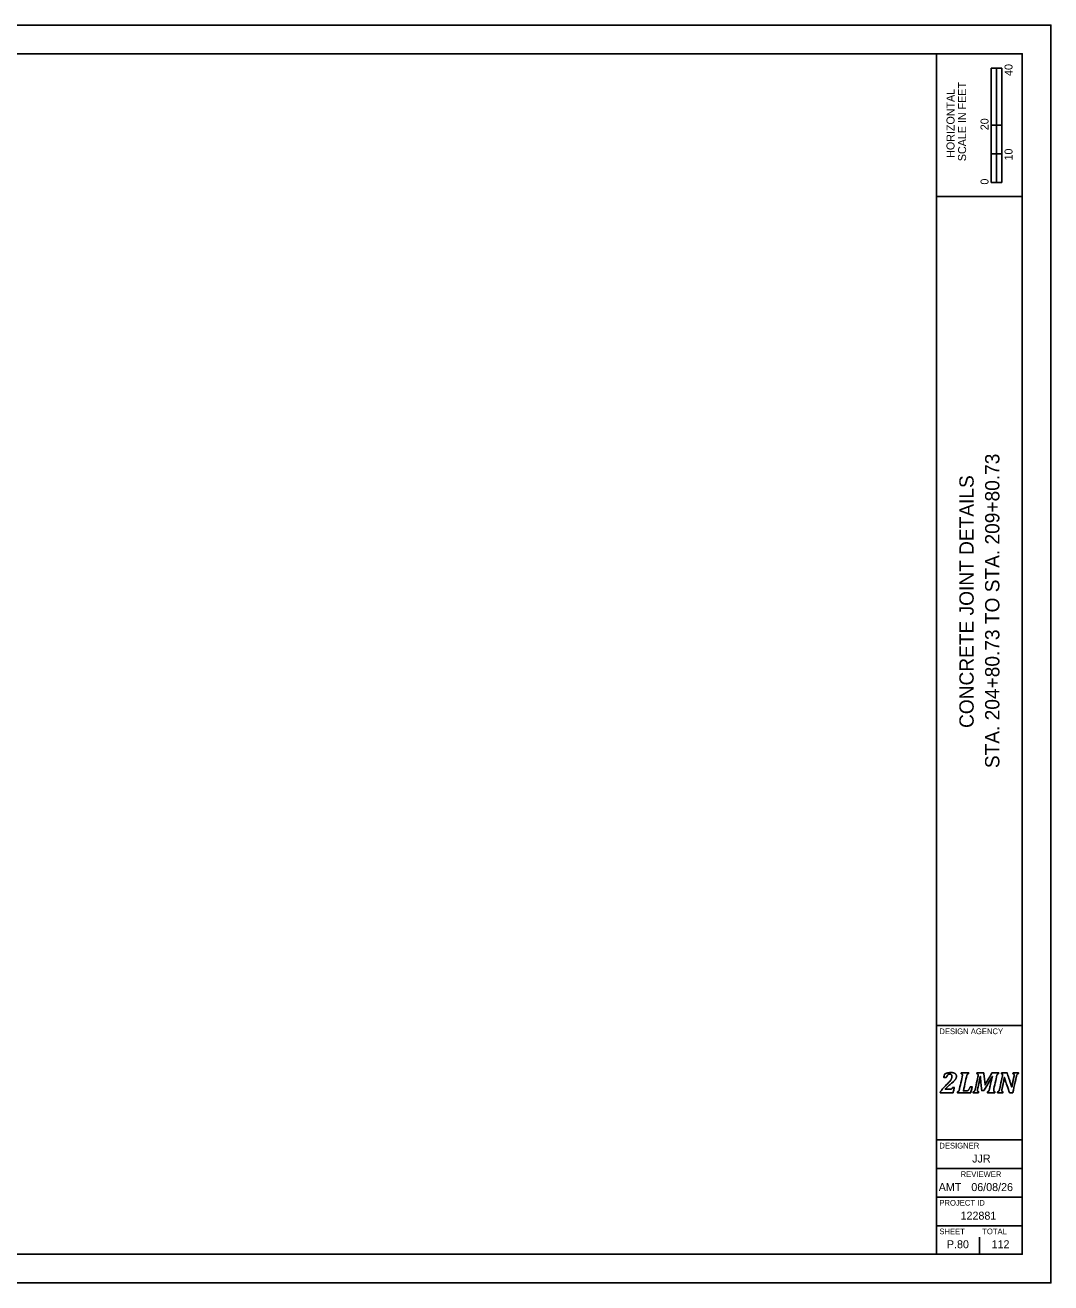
# Model space of a CAD drawing. Extents: x -1.9 to 34, y 0 to 22.
# Drawn here: x 16.06 to 34, y 0 to 22 of the extents above; entities that cross this region are included whole.
import ezdxf

# ---------------------------------------------------------------- set-up
doc = ezdxf.new("R2010")
doc.units = 0
for name, color, linetype in [('SH_Border', 7, 'Continuous'), ('SH_Cut_Line', 7, 'Continuous'), ('SH_Data', 7, 'Continuous')]:
    doc.layers.add(name, color=color, linetype=linetype)

msp = doc.modelspace()

# ---------------------------------------------------------------- linework, layer by layer
at = {"layer": 'SH_Border'}
for p, q in [((32, 0.5), (32, 21.5)), ((32, 19), (33.5, 19)), ((32, 4.5), (33.5, 4.5)), ((32, 2.5), (33.5, 2.5)), ((32, 2), (33.5, 2)), ((32, 1.5), (33.5, 1.5)), ((32, 1), (33.5, 1))]:
    msp.add_line(p, q, dxfattribs=at)
msp.add_lwpolyline([(1.5, 21.5), (33.5, 21.5), (33.5, 0.5), (1.5, 0.5)], close=True, dxfattribs=at)
at = {"layer": 'SH_Cut_Line'}
msp.add_lwpolyline([(0, 0), (34, 0), (34, 22), (0, 22)], close=True, dxfattribs=at)
at = {"layer": 'SH_Data'}
for p, q in [((32.957, 19.25), (32.957, 21.25)), ((33.144, 21.25), (32.957, 21.25)), ((32.957, 20.25), (32.957, 21.25)), ((32.957, 21.25), (33.05, 21.25)), ((33.05, 21.25), (33.051, 21.25)), ((33.051, 21.25), (33.051, 20.25)), ((33.144, 21.25), (33.144, 19.25)), ((33.051, 20.25), (32.957, 20.25)), ((33.143, 20.25), (33.05, 20.25)), ((33.05, 20.25), (33.05, 19.75)), ((33.143, 19.75), (33.143, 20.25)), ((33.05, 19.75), (32.957, 19.75)), ((32.957, 19.75), (32.957, 19.25)), ((33.05, 19.25), (33.05, 19.75)), ((33.05, 19.75), (33.143, 19.75)), ((33.144, 19.25), (32.957, 19.25)), ((32.957, 19.25), (33.05, 19.25)), ((32.75, 3.5), (32.75, 3.5)), ((32.375, 0.675), (32.375, 0.675)), ((32.75, 0.5), (32.75, 0.8))]:
    msp.add_line(p, q, dxfattribs=at)
for points in [[(32.237, 3.388), (32.246, 3.388), (32.253, 3.389), (32.258, 3.39), (32.263, 3.392), (32.267, 3.394), (32.27, 3.397), (32.273, 3.401), (32.277, 3.408), (32.281, 3.417), (32.281, 3.417), (32.312, 3.417), (32.312, 3.417), (32.312, 3.417), (32.29, 3.326), (32.29, 3.326), (32.29, 3.326), (32.066, 3.326), (32.066, 3.326), (32.066, 3.326), (32.069, 3.343), (32.069, 3.343), (32.078, 3.358), (32.091, 3.375), (32.106, 3.394), (32.122, 3.412), (32.144, 3.435), (32.172, 3.462), (32.197, 3.486), (32.217, 3.506), (32.23, 3.521), (32.243, 3.537), (32.253, 3.551), (32.259, 3.566), (32.266, 3.58), (32.269, 3.595), (32.269, 3.61), (32.269, 3.622), (32.266, 3.632), (32.26, 3.64), (32.253, 3.647), (32.245, 3.65), (32.234, 3.65), (32.22, 3.65), (32.208, 3.646), (32.198, 3.636), (32.188, 3.627), (32.18, 3.613), (32.172, 3.593), (32.172, 3.593), (32.126, 3.593), (32.126, 3.593), (32.126, 3.593), (32.14, 3.654), (32.14, 3.654), (32.166, 3.663), (32.188, 3.669), (32.205, 3.673), (32.223, 3.676), (32.24, 3.678), (32.258, 3.678), (32.278, 3.678), (32.295, 3.675), (32.309, 3.669), (32.322, 3.664), (32.332, 3.656), (32.339, 3.646), (32.345, 3.637), (32.348, 3.626), (32.348, 3.613), (32.348, 3.602), (32.346, 3.591), (32.342, 3.581), (32.339, 3.571), (32.333, 3.56), (32.324, 3.549), (32.315, 3.539), (32.304, 3.526), (32.289, 3.513), (32.275, 3.499), (32.254, 3.482), (32.228, 3.46), (32.216, 3.45), (32.202, 3.438), (32.188, 3.425), (32.174, 3.412), (32.162, 3.4), (32.154, 3.391), (32.154, 3.391), (32.153, 3.388), (32.153, 3.388), (32.153, 3.388), (32.237, 3.388), (32.237, 3.388)], [(32.237, 3.388), (32.237, 3.388), (32.153, 3.388), (32.153, 3.388), (32.153, 3.388), (32.154, 3.391), (32.154, 3.391), (32.162, 3.4), (32.174, 3.412), (32.188, 3.425), (32.202, 3.438), (32.216, 3.45), (32.228, 3.46), (32.254, 3.482), (32.275, 3.499), (32.289, 3.513), (32.304, 3.526), (32.315, 3.539), (32.324, 3.549), (32.333, 3.56), (32.339, 3.571), (32.342, 3.581), (32.346, 3.591), (32.348, 3.602), (32.348, 3.613), (32.348, 3.626), (32.345, 3.637), (32.339, 3.646), (32.332, 3.656), (32.322, 3.664), (32.309, 3.669), (32.295, 3.675), (32.278, 3.678), (32.258, 3.678), (32.24, 3.678), (32.223, 3.676), (32.205, 3.673), (32.188, 3.669), (32.166, 3.663), (32.14, 3.654), (32.14, 3.654), (32.126, 3.593), (32.126, 3.593), (32.126, 3.593), (32.172, 3.593), (32.172, 3.593), (32.18, 3.613), (32.188, 3.627), (32.198, 3.636), (32.208, 3.646), (32.22, 3.65), (32.234, 3.65), (32.245, 3.65), (32.253, 3.647), (32.26, 3.64), (32.266, 3.632), (32.269, 3.622), (32.269, 3.61), (32.269, 3.595), (32.266, 3.58), (32.259, 3.566), (32.253, 3.551), (32.243, 3.537), (32.23, 3.521), (32.217, 3.506), (32.197, 3.486), (32.172, 3.462), (32.144, 3.435), (32.122, 3.412), (32.106, 3.394), (32.091, 3.375), (32.078, 3.358), (32.069, 3.343), (32.069, 3.343), (32.066, 3.326), (32.066, 3.326), (32.066, 3.326), (32.29, 3.326), (32.29, 3.326), (32.29, 3.326), (32.312, 3.417), (32.312, 3.417), (32.312, 3.417), (32.281, 3.417), (32.281, 3.417), (32.277, 3.408), (32.273, 3.401), (32.27, 3.397), (32.267, 3.394), (32.263, 3.392), (32.258, 3.39), (32.253, 3.389), (32.246, 3.388), (32.237, 3.388)], [(32.518, 3.356), (32.527, 3.356), (32.533, 3.357), (32.538, 3.358), (32.542, 3.36), (32.546, 3.362), (32.55, 3.365), (32.554, 3.368), (32.558, 3.372), (32.562, 3.377), (32.567, 3.382), (32.571, 3.388), (32.576, 3.397), (32.58, 3.405), (32.585, 3.415), (32.589, 3.427), (32.589, 3.427), (32.624, 3.427), (32.624, 3.427), (32.624, 3.427), (32.598, 3.326), (32.598, 3.326), (32.598, 3.326), (32.365, 3.326), (32.365, 3.326), (32.365, 3.326), (32.369, 3.343), (32.369, 3.343), (32.376, 3.345), (32.381, 3.348), (32.385, 3.351), (32.389, 3.355), (32.392, 3.36), (32.395, 3.366), (32.398, 3.373), (32.4, 3.382), (32.403, 3.395), (32.403, 3.395), (32.449, 3.605), (32.449, 3.605), (32.452, 3.615), (32.453, 3.625), (32.453, 3.635), (32.453, 3.642), (32.451, 3.647), (32.448, 3.651), (32.444, 3.654), (32.439, 3.656), (32.432, 3.657), (32.432, 3.657), (32.435, 3.674), (32.435, 3.674), (32.435, 3.674), (32.563, 3.674), (32.563, 3.674), (32.563, 3.674), (32.559, 3.657), (32.559, 3.657), (32.552, 3.655), (32.547, 3.652), (32.543, 3.649), (32.539, 3.645), (32.536, 3.64), (32.533, 3.634), (32.531, 3.627), (32.528, 3.618), (32.525, 3.605), (32.525, 3.605), (32.47, 3.356), (32.47, 3.356), (32.47, 3.356), (32.518, 3.356), (32.518, 3.356)], [(32.518, 3.356), (32.518, 3.356), (32.47, 3.356), (32.47, 3.356), (32.47, 3.356), (32.525, 3.605), (32.525, 3.605), (32.528, 3.618), (32.531, 3.627), (32.533, 3.634), (32.536, 3.64), (32.539, 3.645), (32.543, 3.649), (32.547, 3.652), (32.552, 3.655), (32.559, 3.657), (32.559, 3.657), (32.563, 3.674), (32.563, 3.674), (32.563, 3.674), (32.435, 3.674), (32.435, 3.674), (32.435, 3.674), (32.432, 3.657), (32.432, 3.657), (32.439, 3.656), (32.444, 3.654), (32.448, 3.651), (32.451, 3.647), (32.453, 3.642), (32.453, 3.635), (32.453, 3.625), (32.452, 3.615), (32.449, 3.605), (32.449, 3.605), (32.403, 3.395), (32.403, 3.395), (32.4, 3.382), (32.398, 3.373), (32.395, 3.366), (32.392, 3.36), (32.389, 3.355), (32.385, 3.351), (32.381, 3.348), (32.376, 3.345), (32.369, 3.343), (32.369, 3.343), (32.365, 3.326), (32.365, 3.326), (32.365, 3.326), (32.598, 3.326), (32.598, 3.326), (32.598, 3.326), (32.624, 3.427), (32.624, 3.427), (32.624, 3.427), (32.589, 3.427), (32.589, 3.427), (32.585, 3.415), (32.58, 3.405), (32.576, 3.397), (32.571, 3.388), (32.567, 3.382), (32.562, 3.377), (32.558, 3.372), (32.554, 3.368), (32.55, 3.365), (32.546, 3.362), (32.542, 3.36), (32.538, 3.358), (32.533, 3.357), (32.527, 3.356), (32.518, 3.356)], [(32.829, 3.674), (32.829, 3.674), (32.849, 3.461), (32.849, 3.461), (32.849, 3.461), (32.969, 3.674), (32.969, 3.674), (32.969, 3.674), (33.087, 3.674), (33.087, 3.674), (33.087, 3.674), (33.084, 3.657), (33.084, 3.657), (33.077, 3.655), (33.071, 3.652), (33.067, 3.649), (33.064, 3.645), (33.06, 3.64), (33.058, 3.634), (33.055, 3.627), (33.052, 3.618), (33.05, 3.605), (33.05, 3.605), (33.003, 3.395), (33.003, 3.395), (33.002, 3.39), (33.002, 3.387), (33.001, 3.384), (33.001, 3.382), (33.001, 3.379), (33, 3.376), (33, 3.373), (33, 3.369), (33, 3.365), (33, 3.358), (33.002, 3.353), (33.005, 3.349), (33.008, 3.346), (33.014, 3.344), (33.021, 3.343), (33.021, 3.343), (33.018, 3.326), (33.018, 3.326), (33.018, 3.326), (32.89, 3.326), (32.89, 3.326), (32.89, 3.326), (32.893, 3.343), (32.893, 3.343), (32.9, 3.345), (32.906, 3.348), (32.91, 3.351), (32.914, 3.355), (32.917, 3.36), (32.919, 3.366), (32.922, 3.373), (32.925, 3.382), (32.928, 3.395), (32.928, 3.395), (32.951, 3.502), (32.951, 3.502), (32.954, 3.513), (32.957, 3.529), (32.962, 3.548), (32.967, 3.568), (32.972, 3.588), (32.978, 3.609), (32.978, 3.609), (32.973, 3.609), (32.973, 3.609), (32.965, 3.594), (32.957, 3.579), (32.948, 3.563), (32.948, 3.563), (32.833, 3.364), (32.833, 3.364), (32.833, 3.364), (32.792, 3.364), (32.792, 3.364), (32.792, 3.364), (32.775, 3.518), (32.775, 3.518), (32.773, 3.537), (32.772, 3.554), (32.77, 3.569), (32.769, 3.583), (32.768, 3.597), (32.768, 3.611), (32.768, 3.611), (32.764, 3.611), (32.764, 3.611), (32.761, 3.596), (32.758, 3.578), (32.755, 3.558), (32.751, 3.538), (32.747, 3.521), (32.744, 3.507), (32.744, 3.507), (32.72, 3.395), (32.72, 3.395), (32.719, 3.39), (32.718, 3.387), (32.718, 3.384), (32.717, 3.382), (32.717, 3.379), (32.717, 3.376), (32.717, 3.373), (32.716, 3.369), (32.716, 3.365), (32.716, 3.358), (32.718, 3.353), (32.721, 3.349), (32.725, 3.346), (32.73, 3.344), (32.738, 3.343), (32.738, 3.343), (32.734, 3.326), (32.734, 3.326), (32.734, 3.326), (32.641, 3.326), (32.641, 3.326), (32.641, 3.326), (32.644, 3.343), (32.644, 3.343), (32.651, 3.345), (32.657, 3.348), (32.661, 3.351), (32.665, 3.355), (32.668, 3.36), (32.67, 3.366), (32.673, 3.373), (32.676, 3.382), (32.679, 3.395), (32.679, 3.395), (32.725, 3.605), (32.725, 3.605), (32.727, 3.615), (32.728, 3.625), (32.728, 3.635), (32.728, 3.642), (32.727, 3.647), (32.723, 3.651), (32.72, 3.654), (32.715, 3.656), (32.707, 3.657), (32.707, 3.657), (32.711, 3.674), (32.711, 3.674), (32.711, 3.674), (32.829, 3.674), (32.829, 3.674)], [(32.829, 3.674), (32.829, 3.674), (32.711, 3.674), (32.711, 3.674), (32.711, 3.674), (32.707, 3.657), (32.707, 3.657), (32.715, 3.656), (32.72, 3.654), (32.723, 3.651), (32.727, 3.647), (32.728, 3.642), (32.728, 3.635), (32.728, 3.625), (32.727, 3.615), (32.725, 3.605), (32.725, 3.605), (32.679, 3.395), (32.679, 3.395), (32.676, 3.382), (32.673, 3.373), (32.67, 3.366), (32.668, 3.36), (32.665, 3.355), (32.661, 3.351), (32.657, 3.348), (32.651, 3.345), (32.644, 3.343), (32.644, 3.343), (32.641, 3.326), (32.641, 3.326), (32.641, 3.326), (32.734, 3.326), (32.734, 3.326), (32.734, 3.326), (32.738, 3.343), (32.738, 3.343), (32.73, 3.344), (32.725, 3.346), (32.721, 3.349), (32.718, 3.353), (32.716, 3.358), (32.716, 3.365), (32.716, 3.369), (32.717, 3.373), (32.717, 3.376), (32.717, 3.379), (32.717, 3.382), (32.718, 3.384), (32.718, 3.387), (32.719, 3.39), (32.72, 3.395), (32.72, 3.395), (32.744, 3.507), (32.744, 3.507), (32.747, 3.521), (32.751, 3.538), (32.755, 3.558), (32.758, 3.578), (32.761, 3.596), (32.764, 3.611), (32.764, 3.611), (32.768, 3.611), (32.768, 3.611), (32.768, 3.597), (32.769, 3.583), (32.77, 3.569), (32.772, 3.554), (32.773, 3.537), (32.775, 3.518), (32.775, 3.518), (32.792, 3.364), (32.792, 3.364), (32.792, 3.364), (32.833, 3.364), (32.833, 3.364), (32.833, 3.364), (32.948, 3.563), (32.948, 3.563), (32.957, 3.579), (32.965, 3.594), (32.973, 3.609), (32.973, 3.609), (32.978, 3.609), (32.978, 3.609), (32.972, 3.588), (32.967, 3.568), (32.962, 3.548), (32.957, 3.529), (32.954, 3.513), (32.951, 3.502), (32.951, 3.502), (32.928, 3.395), (32.928, 3.395), (32.925, 3.382), (32.922, 3.373), (32.919, 3.366), (32.917, 3.36), (32.914, 3.355), (32.91, 3.351), (32.906, 3.348), (32.9, 3.345), (32.893, 3.343), (32.893, 3.343), (32.89, 3.326), (32.89, 3.326), (32.89, 3.326), (33.018, 3.326), (33.018, 3.326), (33.018, 3.326), (33.021, 3.343), (33.021, 3.343), (33.014, 3.344), (33.008, 3.346), (33.005, 3.349), (33.002, 3.353), (33, 3.358), (33, 3.365), (33, 3.369), (33, 3.373), (33, 3.376), (33.001, 3.379), (33.001, 3.382), (33.001, 3.384), (33.002, 3.387), (33.002, 3.39), (33.003, 3.395), (33.003, 3.395), (33.05, 3.605), (33.05, 3.605), (33.052, 3.618), (33.055, 3.627), (33.058, 3.634), (33.06, 3.64), (33.064, 3.645), (33.067, 3.649), (33.071, 3.652), (33.077, 3.655), (33.084, 3.657), (33.084, 3.657), (33.087, 3.674), (33.087, 3.674), (33.087, 3.674), (32.969, 3.674), (32.969, 3.674), (32.969, 3.674), (32.849, 3.461), (32.849, 3.461), (32.849, 3.461), (32.829, 3.674), (32.829, 3.674)], [(33.137, 3.674), (33.137, 3.674), (33.234, 3.674), (33.234, 3.674), (33.234, 3.674), (33.283, 3.53), (33.283, 3.53), (33.296, 3.49), (33.307, 3.456), (33.315, 3.426), (33.315, 3.426), (33.318, 3.426), (33.318, 3.426), (33.323, 3.455), (33.329, 3.488), (33.337, 3.523), (33.337, 3.523), (33.355, 3.605), (33.355, 3.605), (33.357, 3.615), (33.358, 3.625), (33.358, 3.635), (33.358, 3.642), (33.357, 3.647), (33.353, 3.651), (33.35, 3.654), (33.345, 3.656), (33.337, 3.657), (33.337, 3.657), (33.341, 3.674), (33.341, 3.674), (33.341, 3.674), (33.434, 3.674), (33.434, 3.674), (33.434, 3.674), (33.431, 3.657), (33.431, 3.657), (33.424, 3.655), (33.418, 3.652), (33.414, 3.649), (33.41, 3.645), (33.407, 3.64), (33.405, 3.634), (33.402, 3.627), (33.399, 3.618), (33.396, 3.605), (33.396, 3.605), (33.335, 3.326), (33.335, 3.326), (33.335, 3.326), (33.277, 3.326), (33.277, 3.326), (33.277, 3.326), (33.216, 3.504), (33.216, 3.504), (33.211, 3.518), (33.207, 3.531), (33.204, 3.543), (33.2, 3.556), (33.195, 3.571), (33.19, 3.59), (33.19, 3.59), (33.186, 3.59), (33.186, 3.59), (33.185, 3.579), (33.182, 3.563), (33.179, 3.543), (33.175, 3.523), (33.17, 3.501), (33.165, 3.478), (33.165, 3.478), (33.147, 3.395), (33.147, 3.395), (33.146, 3.39), (33.145, 3.387), (33.145, 3.384), (33.144, 3.382), (33.144, 3.379), (33.144, 3.376), (33.143, 3.373), (33.143, 3.369), (33.143, 3.365), (33.143, 3.358), (33.145, 3.353), (33.148, 3.349), (33.152, 3.346), (33.157, 3.344), (33.164, 3.343), (33.164, 3.343), (33.161, 3.326), (33.161, 3.326), (33.161, 3.326), (33.067, 3.326), (33.067, 3.326), (33.067, 3.326), (33.071, 3.343), (33.071, 3.343), (33.078, 3.345), (33.083, 3.348), (33.087, 3.351), (33.091, 3.355), (33.094, 3.36), (33.097, 3.366), (33.1, 3.373), (33.102, 3.382), (33.105, 3.395), (33.105, 3.395), (33.151, 3.605), (33.151, 3.605), (33.154, 3.615), (33.155, 3.625), (33.155, 3.635), (33.155, 3.642), (33.153, 3.647), (33.15, 3.651), (33.146, 3.654), (33.141, 3.656), (33.134, 3.657), (33.134, 3.657), (33.137, 3.674), (33.137, 3.674)], [(33.137, 3.674), (33.137, 3.674), (33.134, 3.657), (33.134, 3.657), (33.141, 3.656), (33.146, 3.654), (33.15, 3.651), (33.153, 3.647), (33.155, 3.642), (33.155, 3.635), (33.155, 3.625), (33.154, 3.615), (33.151, 3.605), (33.151, 3.605), (33.105, 3.395), (33.105, 3.395), (33.102, 3.382), (33.1, 3.373), (33.097, 3.366), (33.094, 3.36), (33.091, 3.355), (33.087, 3.351), (33.083, 3.348), (33.078, 3.345), (33.071, 3.343), (33.071, 3.343), (33.067, 3.326), (33.067, 3.326), (33.067, 3.326), (33.161, 3.326), (33.161, 3.326), (33.161, 3.326), (33.164, 3.343), (33.164, 3.343), (33.157, 3.344), (33.152, 3.346), (33.148, 3.349), (33.145, 3.353), (33.143, 3.358), (33.143, 3.365), (33.143, 3.369), (33.143, 3.373), (33.144, 3.376), (33.144, 3.379), (33.144, 3.382), (33.145, 3.384), (33.145, 3.387), (33.146, 3.39), (33.147, 3.395), (33.147, 3.395), (33.165, 3.478), (33.165, 3.478), (33.17, 3.501), (33.175, 3.523), (33.179, 3.543), (33.182, 3.563), (33.185, 3.579), (33.186, 3.59), (33.186, 3.59), (33.19, 3.59), (33.19, 3.59), (33.195, 3.571), (33.2, 3.556), (33.204, 3.543), (33.207, 3.531), (33.211, 3.518), (33.216, 3.504), (33.216, 3.504), (33.277, 3.326), (33.277, 3.326), (33.277, 3.326), (33.335, 3.326), (33.335, 3.326), (33.335, 3.326), (33.396, 3.605), (33.396, 3.605), (33.399, 3.618), (33.402, 3.627), (33.405, 3.634), (33.407, 3.64), (33.41, 3.645), (33.414, 3.649), (33.418, 3.652), (33.424, 3.655), (33.431, 3.657), (33.431, 3.657), (33.434, 3.674), (33.434, 3.674), (33.434, 3.674), (33.341, 3.674), (33.341, 3.674), (33.341, 3.674), (33.337, 3.657), (33.337, 3.657), (33.345, 3.656), (33.35, 3.654), (33.353, 3.651), (33.357, 3.647), (33.358, 3.642), (33.358, 3.635), (33.358, 3.625), (33.357, 3.615), (33.355, 3.605), (33.355, 3.605), (33.337, 3.523), (33.337, 3.523), (33.329, 3.488), (33.323, 3.455), (33.318, 3.426), (33.318, 3.426), (33.315, 3.426), (33.315, 3.426), (33.307, 3.456), (33.296, 3.49), (33.283, 3.53), (33.283, 3.53), (33.234, 3.674), (33.234, 3.674), (33.234, 3.674), (33.137, 3.674), (33.137, 3.674)]]:
    msp.add_open_spline(points, degree=3, dxfattribs=at)

# ---------------------------------------------------------------- texts
for s, height, p in [('40', 0.14, (33.33, 21.112)), ('SCALE IN FEET', 0.14, (32.517, 19.621)), ('HORIZONTAL', 0.14, (32.315, 19.679)), ('20', 0.14, (32.91, 20.162)), ('10', 0.14, (33.33, 19.633)), ('0', 0.14, (32.91, 19.211)), ('STA. 204+80.73 TO STA. 209+80.73', 0.25, (33.1, 9.004)), ('CONCRETE JOINT DETAILS', 0.25, (32.65, 9.706))]:
    msp.add_text(s, height=height, rotation=90, dxfattribs=at).set_placement(p)
for s, height, p in [('DESIGN AGENCY', 0.1, (32.05, 4.35)), ('DESIGNER', 0.1, (32.05, 2.35)), ('JJR', 0.14, (32.624, 2.105)), ('REVIEWER', 0.1, (32.422, 1.85)), ('AMT', 0.14, (32.039, 1.605)), ('06/08/26', 0.14, (32.609, 1.605)), ('PROJECT ID', 0.1, (32.05, 1.35)), ('122881', 0.14, (32.421, 1.105)), ('SHEET', 0.1, (32.05, 0.85)), ('TOTAL', 0.1, (32.8, 0.85)), ('P.80', 0.14, (32.182, 0.605)), ('112', 0.14, (32.964, 0.605))]:
    msp.add_text(s, height=height, dxfattribs=at).set_placement(p)

doc.saveas('drawing.dxf')
